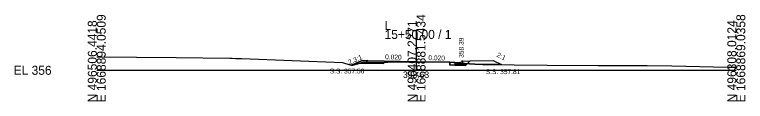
# Model space of a CAD drawing. Extents: x -26 to 203, y -10 to 5517.
# Drawn here: x -25.7 to 202.8, y 5490.3 to 5517.4 of the extents above; entities that cross this region are included whole.
import ezdxf

# ---------------------------------------------------------------- set-up
doc = ezdxf.new("R2010")
doc.units = 0
for name, color, linetype in [('Exist Cross Section Cell', 7, 'Continuous'), ('Exist XS Center Line Elevation Label', 7, 'Continuous'), ('Exist XS Ground Line', 7, 'Continuous'), ('Prop XS Earthwork Shape', 7, 'Continuous'), ('Prop XS Finish Grade', 7, 'Continuous'), ('Prop XS Finish Grade CurbGutter', 7, 'Continuous'), ('Prop XS Finish Grade Earthwork', 7, 'Continuous'), ('Prop XS Finish Grade Pavement', 7, 'Continuous'), ('Prop XS Geopak Shape', 7, 'Continuous'), ('Prop XS Hydro Elevations', 7, 'Continuous'), ('Prop XS Pvmt Edge Slope', 7, 'Continuous'), ('Prop XS SE Text', 7, 'Continuous'), ('Prop XS Side Slope Text', 7, 'Continuous'), ('Prop XS SS Elevation Text', 7, 'Continuous'), ('Prop XS Subgrade CurbGutter', 7, 'Continuous'), ('Prop XS Subgrade Earthwork', 7, 'Continuous')]:
    doc.layers.add(name, color=color, linetype=linetype)

msp = doc.modelspace()

# ---------------------------------------------------------------- linework, layer by layer
at = {"layer": 'Exist Cross Section Cell'}
for p, q in [((100, 5500), (100, 5512.6)), ((0, 5500), (100, 5500)), ((100, 5500), (200, 5500))]:
    msp.add_line(p, q, dxfattribs=at)
at = {"layer": 'Exist XS Ground Line'}
for p, q in [((0, 5504.2), (24.85, 5503.98)), ((24.85, 5503.98), (41.59, 5503.78)), ((41.59, 5503.78), (42.38, 5503.75)), ((42.38, 5503.75), (43.45, 5503.72)), ((43.45, 5503.72), (45.36, 5503.68)), ((45.36, 5503.68), (76.81, 5502.43)), ((76.81, 5502.43), (77.49, 5502.24)), ((77.49, 5502.24), (79.53, 5501.56)), ((79.53, 5501.56), (80.08, 5501.65)), ((80.08, 5501.65), (83.1, 5502.43)), ((83.1, 5502.43), (83.49, 5502.44)), ((83.49, 5502.44), (84.56, 5502.46)), ((84.56, 5502.46), (97.63, 5502.64)), ((97.63, 5502.64), (98.82, 5502.66)), ((98.82, 5502.66), (99.55, 5502.64)), ((99.55, 5502.64), (100, 5502.63)), ((100, 5502.63), (110.4, 5502.5)), ((110.4, 5502.5), (111.68, 5502.46)), ((111.68, 5502.46), (113.37, 5502.27)), ((113.37, 5502.27), (118.22, 5501.89)), ((118.22, 5501.89), (120.7, 5501.85)), ((120.7, 5501.85), (124.44, 5501.84)), ((124.44, 5501.84), (130.48, 5501.74)), ((130.48, 5501.74), (140.87, 5501.56)), ((140.87, 5501.56), (156.76, 5501.51)), ((156.76, 5501.51), (172.17, 5501.52)), ((172.17, 5501.52), (179.86, 5501.36)), ((179.86, 5501.36), (197.22, 5500.99)), ((197.22, 5500.99), (200, 5500.93))]:
    msp.add_line(p, q, dxfattribs=at)
at = {"layer": 'Prop XS Earthwork Shape'}
for points in [[(116.74, 5502.93), (124, 5503.09), (126.56, 5501.81), (124.44, 5501.84), (120.7, 5501.85), (118.22, 5501.89), (115.88, 5502.07)], [(79.53, 5501.56), (80.08, 5501.65), (81.67, 5502.06), (80.59, 5502.02)], [(84.56, 5502.46), (89.63, 5502.53), (89.63, 5502.04), (83.85, 5502.15), (81.67, 5502.06), (83.1, 5502.43), (83.49, 5502.44)], [(112, 5501.59), (110.4, 5501.62), (110.4, 5502.5), (111.68, 5502.46), (113.37, 5502.27), (115.88, 5502.07), (115.33, 5501.53)]]:
    msp.add_lwpolyline(points, close=True, dxfattribs=at)
at = {"layer": 'Prop XS Finish Grade'}
for p, q in [((82.77, 5502.97), (80.59, 5502.02)), ((84.77, 5503.05), (82.77, 5502.97)), ((114.5, 5502.89), (116.74, 5502.93))]:
    msp.add_line(p, q, dxfattribs=at)
at = {"layer": 'Prop XS Finish Grade CurbGutter'}
for p, q in [((112, 5502.51), (113.75, 5502.4)), ((113.75, 5502.4), (113.87, 5502.42)), ((113.87, 5502.42), (113.97, 5502.52)), ((113.97, 5502.52), (114.03, 5502.77)), ((114.03, 5502.77), (114.12, 5502.86)), ((114.25, 5502.89), (114.12, 5502.86)), ((114.5, 5502.89), (114.25, 5502.89))]:
    msp.add_line(p, q, dxfattribs=at)
at = {"layer": 'Prop XS Finish Grade Earthwork'}
for p, q in [((116.74, 5502.93), (124, 5503.09)), ((124, 5503.09), (126.56, 5501.81)), ((80.59, 5502.02), (79.53, 5501.56))]:
    msp.add_line(p, q, dxfattribs=at)
at = {"layer": 'Prop XS Finish Grade Pavement'}
for p, q in [((84.77, 5503.05), (100, 5502.75)), ((100, 5502.75), (112, 5502.51))]:
    msp.add_line(p, q, dxfattribs=at)
at = {"layer": 'Prop XS Geopak Shape'}
msp.add_lwpolyline([(113.97, 5502.52), (114.03, 5502.77), (114.12, 5502.86), (114.25, 5502.89), (114.5, 5502.89), (116.74, 5502.93), (124, 5503.09), (126.56, 5501.81), (124.44, 5501.84), (120.7, 5501.85), (118.22, 5501.89), (113.37, 5502.27), (111.68, 5502.46), (110.4, 5502.5), (100, 5502.63), (99.55, 5502.64), (98.82, 5502.66), (97.63, 5502.64), (84.56, 5502.46), (83.49, 5502.44), (83.1, 5502.43), (80.08, 5501.65), (79.53, 5501.56), (80.59, 5502.02), (82.77, 5502.97), (84.77, 5503.05), (100, 5502.75), (112, 5502.51), (113.75, 5502.4), (113.87, 5502.42)], close=True, dxfattribs=at)
at = {"layer": 'Prop XS Pvmt Edge Slope'}
for p, q in [((84.77, 5503.05), (83.85, 5502.15)), ((114.5, 5501.88), (115, 5501.87)), ((115, 5501.87), (115.33, 5501.53))]:
    msp.add_line(p, q, dxfattribs=at)
at = {"layer": 'Prop XS Subgrade CurbGutter'}
for p, q in [((112, 5502.51), (112, 5501.93)), ((112, 5501.93), (114.5, 5501.88)), ((114.5, 5501.88), (114.5, 5502.89))]:
    msp.add_line(p, q, dxfattribs=at)
at = {"layer": 'Prop XS Subgrade Earthwork'}
for p, q in [((83.85, 5502.15), (80.59, 5502.02)), ((89.63, 5502.04), (83.85, 5502.15)), ((84.77, 5502.13), (84.77, 5502.14)), ((89.63, 5502.53), (89.63, 5502.04)), ((110.4, 5502.5), (110.4, 5501.62)), ((112, 5501.59), (110.4, 5501.62)), ((112, 5501.59), (112, 5501.59)), ((112, 5501.59), (115.33, 5501.53)), ((115.33, 5501.53), (116.74, 5502.93))]:
    msp.add_line(p, q, dxfattribs=at)

# ---------------------------------------------------------------- texts
at = {"layer": 'Exist Cross Section Cell'}
for s, p in [('E 1668894.0509', (2.8, 5490)), ('E 1668881.5434', (102.8, 5490)), ('E 1668869.0358', (202.8, 5490)), ('N 496506.4418', (0, 5490)), ('N 496407.2271', (100, 5490)), ('N 496308.0124', (200, 5490))]:
    msp.add_text(s, height=2.8, rotation=90, dxfattribs=at).set_placement(p)
for s, p in [('L', (90, 5512.6)), ('15+50.00 / 1', (90, 5509.8)), ('EL 356', (-26, 5498.6))]:
    msp.add_text(s, height=2.8, dxfattribs=at).set_placement(p)
at = {"layer": 'Exist XS Center Line Elevation Label'}
msp.add_text('358.63', height=2, dxfattribs=at).set_placement((95.75, 5497.63))
at = {"layer": 'Prop XS Hydro Elevations'}
msp.add_text('358.39', height=1.5, rotation=90, dxfattribs=at).set_placement((114.75, 5503.89))
at = {"layer": 'Prop XS SE Text'}
for p in [(90.16, 5503.45), (103.69, 5503.18)]:
    msp.add_text('0.020', height=1.5, rotation=358.8542, dxfattribs=at).set_placement(p)
at = {"layer": 'Prop XS Side Slope Text'}
for s, rotation, p in [('2:1', 333.4349, (124.89, 5504.32)), ('2.3:1', 23.5012, (78.99, 5501.73))]:
    msp.add_text(s, height=1.5, rotation=rotation, dxfattribs=at).set_placement(p)
at = {"layer": 'Prop XS SS Elevation Text'}
for s, p in [('S.S. 357.56', (72.85, 5499.02)), ('S.S. 357.81', (121.65, 5498.81))]:
    msp.add_text(s, height=1.5, dxfattribs=at).set_placement(p)

doc.saveas('drawing.dxf')
